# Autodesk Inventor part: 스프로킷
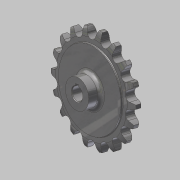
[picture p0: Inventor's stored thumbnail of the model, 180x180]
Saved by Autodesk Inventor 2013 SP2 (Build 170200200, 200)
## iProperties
Created: 2016-03
Part Number: 스프로킷
Material: 강철, 탄소
Document SubType Name: Modeling
Designer: mduedu
Density: 7.87 g/cm^3
Mass: 301.857 g
Surface Area: 120.622 cm^2
Volume: 38.3554 cm^3
Author: mduedu
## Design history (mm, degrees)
sketch "스케치1"
  geometry: L1 (0, 5)-(29.5, 5); L2 (29.5, 5)-(29.5, 4.1); L3 (30, 3.6)-(33.625, 3.6); L4 (40, 2)-(40, 0); L5 (40, 0)-(0, 0); L6 (0, 0)-(0, 5); L7 (0, -5)-(29.5, -5); L8 (29.5, -5)-(29.5, -4.1); L9 (30, -3.6)-(33.625, -3.6); L10 (40, -2)-(40, 0); L11 (0, 0)-(0, -5); A1 r 13.5 centre (33.625, -9.9) between (40, 2) and (33.625, 3.6); A2 r 13.5 centre (33.625, 9.9) between (33.625, -3.6) and (40, -2); A3 r 0.5 centre (30, 4.1) between (29.5, 4.1) and (30, 3.6); A4 r 0.5 centre (30, -4.1) between (30, -3.6) and (29.5, -4.1); 2 further points
  constraints: 22 end point, 8 point on circle, 6 symmetric about line, 5 tangent, 4 centre point, 4 parallel, 4 point on line, 1 equal radius, 1 horizontal, 1 perpendicular, 1 other
  dimensions: "d0" = 80 diameter of L4 L6; "d2" = 59 diameter of L2 L6; "d3" = 1.6 vertical distance of L4.start L3.end; "d4" = 3.6 distance from line of L4.end L3; "d5" = 5 distance between parallel lines of L5 L1; "d6" = 13.5 radius of A1; "d15" = 0.5 radius of A3
revolve "회전1" sketch "스케치1" stored, may be unused: angle "d7" = 90 deg
sketch "스케치2" dims "d8" = 65.2, "d11" = 80
  geometry: L1 (0, 0)-(0, 32.6); A1 r 36.57 centre (0, 0) between (-16.231, 32.771) and (0, 36.57); A2 r 3.97 centre (0, 36.57) between (-3.866, 35.665) and (0, 32.6); A3 r 12.7 centre (-16.231, 32.771) between (-3.866, 35.665) and (-5.534, 39.615); A4 r 12.7 centre (16.231, 32.771) between (5.534, 39.615) and (3.866, 35.665); A5 r 3.97 centre (0, 36.57) between (0, 32.6) and (3.866, 35.665); A6 r 40 centre (0, 0) between (5.534, 39.615) and (-5.534, 39.615); 2 further points
  constraints: 12 point on circle, 6 centre point, 4 coincident, 3 symmetric about line, 2 end point, 1 point on line, 1 tangent, 1 vertical, 1 vertical alignment, 7 other
  dimensions: "d10" = 73.14 diameter of A1; "d12" = 12.7 radius of A3
extrude "돌출1" cut sketch "스케치2" stored distance "d13" = 10; taper "d14" = 0 deg
sketch "스케치3"
  geometry: C1 r 11 at (0, 0); 1 further point
  constraints: 1 centre point, 1 coincident
  dimensions: "d19" = 22 diameter of C1
extrude "돌출2" join sketch "스케치3" distance "d20" = 10; taper "d21" = 0 deg
fillet "모깎기1" dims "d22" = 3
sketch "스케치4"
  geometry: L1 (-1.5, 0)-(1.5, 0); L2 (1.5, 0)-(1.5, 6.4); L3 (1.5, 6.4)-(-1.5, 6.4); L4 (-1.5, 6.4)-(-1.5, 0); C1 r 5 at (0, 0); 2 further points
  constraints: 8 end point, 2 coincident, 2 parallel, 1 centre point, 1 horizontal, 1 midpoint, 1 perpendicular
  dimensions: "d23" = 10 diameter of C1; "d25" = 3 distance of L2.end L3.end; "d26" = 6.4 distance of L1.end L2.end
extrude "돌출3" cut sketch "스케치4" stored distance "d27" = 8; taper "d28" = 0 deg
chamfer "모따기1" distance "d29" = 0.5; stored, may be unused: second distance "d30" = 2, angle "d31" = 45 deg
sketch "스케치5" dims "d33" = 50
  geometry: C1 r 1 at (0, 25); 2 further points
  constraints: 2 vertical alignment, 1 centre point, 1 coincident, 2 other
  dimensions: "d32" = 2 diameter of C1
extrude "돌출4" join sketch "스케치5" distance "d34" = 0.5; taper "d35" = 0 deg
node "솔리드1"
pattern_circular "원형 패턴1" dims angle "d17" = 360 deg
